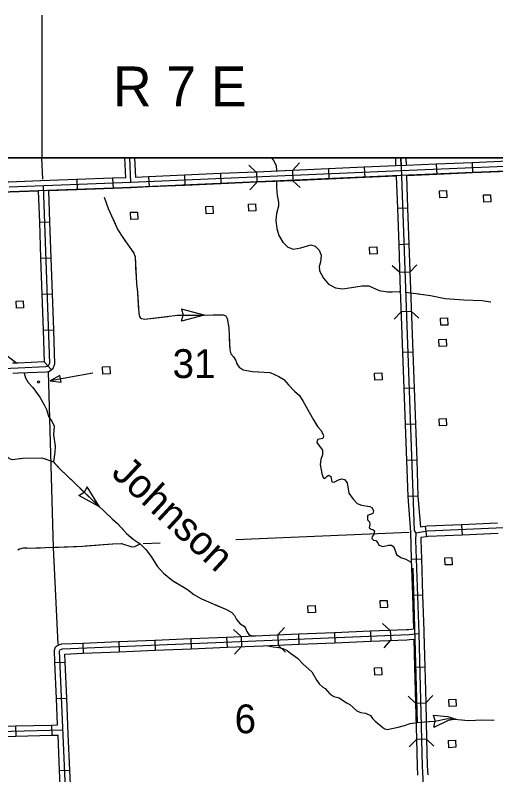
# Model space of a CAD drawing. Extents: x -0.3 to 2.65, y 0 to 1.9.
# Drawn here: x 0.4946 to 0.579, y 0.4334 to 0.5667 of the extents above; entities that cross this region are included whole.
import ezdxf

# ---------------------------------------------------------------- set-up
doc = ezdxf.new("R2010")
doc.units = 0
for name, color, linetype in [('DSN_DRFT_DNC', 7, 'Continuous'), ('Level 11', 7, 'Continuous'), ('Level 12', 7, 'Continuous'), ('Level 14', 7, 'Continuous'), ('Level 15', 7, 'Continuous'), ('Level 18', 7, 'Continuous'), ('Level 19', 7, 'Continuous'), ('Level 20', 7, 'Continuous'), ('Level 29', 7, 'Continuous'), ('Level 6', 7, 'Continuous'), ('SHET_Annotations', 7, 'Continuous')]:
    doc.layers.add(name, color=color, linetype=linetype)

msp = doc.modelspace()

# ---------------------------------------------------------------- linework, layer by layer
at = {"layer": 'DSN_DRFT_DNC'}
msp.add_lwpolyline([(0.38477, 0.54167), (1.0319, 0.54167), (1.0319, 0.1443), (0.38477, 0.1443)], close=True, dxfattribs=at)
at = {"layer": 'Level 11'}
msp.add_line((0.49949, 0.53788), (0.49934, 0.54164), dxfattribs=at)
for points in [[(0.50045, 0.50408), (0.50131, 0.47332), (0.50213, 0.45632)], [(0.53337, 0.47469), (0.56377, 0.476)], [(0.5171, 0.474), (0.52007, 0.47412)]]:
    msp.add_lwpolyline(points, dxfattribs=at)
at = {"layer": 'Level 12'}
for p, q in [((0.52383, 0.51509), (0.52412, 0.51404)), ((0.52781, 0.51407), (0.52383, 0.51509)), ((0.52781, 0.51407), (0.52385, 0.51297)), ((0.52385, 0.51297), (0.52412, 0.51402)), ((0.56802, 0.44388), (0.56835, 0.44283)), ((0.56811, 0.44175), (0.56835, 0.44282))]:
    msp.add_line(p, q, dxfattribs=at)
for points in [[(0.51023, 0.53476), (0.51094, 0.53273), (0.51103, 0.53253)], [(0.5117, 0.5311), (0.51266, 0.52904), (0.51367, 0.52747), (0.51402, 0.52698)], [(0.51493, 0.5257), (0.51548, 0.52493), (0.51567, 0.52426), (0.51584, 0.52116)], [(0.51592, 0.51959), (0.51592, 0.51955), (0.51611, 0.51808), (0.51629, 0.51487)], [(0.56403, 0.51799), (0.56555, 0.51779)], [(0.56712, 0.51758), (0.56755, 0.51752), (0.57009, 0.51699), (0.57179, 0.51686)], [(0.57337, 0.51675), (0.57338, 0.51675), (0.57658, 0.5166), (0.57809, 0.51639)], [(0.5168, 0.51348), (0.51733, 0.51336), (0.5215, 0.51384)], [(0.52307, 0.51402), (0.5231, 0.51402), (0.52781, 0.51407)], [(0.52939, 0.51409), (0.53116, 0.51411), (0.5316, 0.51394), (0.53187, 0.51346), (0.53211, 0.51182), (0.53212, 0.51154)], [(0.5322, 0.50996), (0.53229, 0.50794), (0.53249, 0.50724), (0.53293, 0.50674), (0.53336, 0.50608), (0.53352, 0.50556)], [(0.56802, 0.44388), (0.5706, 0.44366), (0.57198, 0.44316), (0.57065, 0.44292), (0.56811, 0.44174)], [(0.5673, 0.44278), (0.56828, 0.44282), (0.57058, 0.4433), (0.57198, 0.44316)], [(0.57355, 0.443), (0.57417, 0.44294), (0.57674, 0.44304), (0.57828, 0.44302)]]:
    msp.add_lwpolyline(points, dxfattribs=at)
at = {"layer": 'Level 14'}
for p, q in [((0.50729, 0.48396), (0.50677, 0.483)), ((0.50943, 0.48045), (0.50729, 0.48396)), ((0.50582, 0.48242), (0.50676, 0.48299)), ((0.50943, 0.48045), (0.50582, 0.48242))]:
    msp.add_line(p, q, dxfattribs=at)
for points in [[(0.53962, 0.54164), (0.54, 0.54118), (0.54047, 0.5403), (0.54053, 0.53934)], [(0.54052, 0.53747), (0.54052, 0.53645), (0.54063, 0.53504), (0.54087, 0.53388), (0.54084, 0.53315), (0.54051, 0.53186), (0.54041, 0.53063), (0.54059, 0.52927), (0.54091, 0.52803), (0.54162, 0.52684), (0.54251, 0.52597), (0.54351, 0.52564), (0.54479, 0.52583), (0.54651, 0.52636), (0.54731, 0.52615), (0.548, 0.52545), (0.54832, 0.5246), (0.54825, 0.52337), (0.54801, 0.52256), (0.54804, 0.52183), (0.54874, 0.52054), (0.54964, 0.51948), (0.55084, 0.51883), (0.55215, 0.51867), (0.55555, 0.51918), (0.55669, 0.5192), (0.55852, 0.51838), (0.55996, 0.51816), (0.56082, 0.51813), (0.56206, 0.51817), (0.56224, 0.51816)], [(0.51023, 0.53476), (0.51094, 0.53273), (0.51266, 0.52904), (0.51367, 0.52747), (0.51548, 0.52493), (0.51567, 0.52426), (0.51592, 0.51955), (0.51611, 0.51808), (0.51632, 0.51434), (0.51644, 0.51383), (0.51666, 0.51352), (0.51733, 0.51336), (0.5231, 0.51402), (0.53116, 0.51411), (0.5316, 0.51394), (0.53187, 0.51346), (0.53211, 0.51182), (0.53229, 0.50794), (0.53249, 0.50724), (0.53293, 0.50674), (0.53336, 0.50608), (0.53354, 0.5055), (0.53393, 0.50495), (0.53467, 0.50445), (0.53628, 0.50416), (0.5394, 0.50398)], [(0.51023, 0.53476), (0.51094, 0.53273), (0.51266, 0.52904), (0.51367, 0.52747), (0.51548, 0.52493), (0.51567, 0.52426), (0.51592, 0.51955), (0.51611, 0.51808), (0.51632, 0.51434), (0.51644, 0.51383), (0.51666, 0.51352), (0.51733, 0.51336), (0.5231, 0.51402), (0.53116, 0.51411), (0.5316, 0.51394), (0.53187, 0.51346), (0.53211, 0.51182), (0.53229, 0.50794), (0.53249, 0.50724), (0.53293, 0.50674), (0.53336, 0.50608), (0.53354, 0.5055), (0.53393, 0.50495), (0.53467, 0.50445), (0.53628, 0.50416), (0.5394, 0.50398)], [(0.5632, 0.5181), (0.56755, 0.51752), (0.57009, 0.51699), (0.57338, 0.51675), (0.57658, 0.5166), (0.57813, 0.51638)], [(0.5632, 0.5181), (0.56755, 0.51752), (0.57009, 0.51699), (0.57338, 0.51675), (0.57658, 0.5166), (0.57813, 0.51638)], [(0.49222, 0.50768), (0.49487, 0.50571)], [(0.49619, 0.50386), (0.49647, 0.50308), (0.49693, 0.50221), (0.49773, 0.50138), (0.49895, 0.49965), (0.49974, 0.4983), (0.50013, 0.49748), (0.50052, 0.49617), (0.50104, 0.49546), (0.50148, 0.49455), (0.50137, 0.49308), (0.50165, 0.49105), (0.50161, 0.49004), (0.50135, 0.48831)], [(0.53462, 0.50448), (0.53467, 0.50445), (0.53628, 0.50416), (0.53932, 0.50398)], [(0.5394, 0.50398), (0.5409, 0.50331), (0.5418, 0.50277), (0.54258, 0.50182), (0.54365, 0.50071), (0.54453, 0.49995), (0.54521, 0.49889), (0.54697, 0.49567), (0.54768, 0.49453), (0.54828, 0.49387), (0.54868, 0.49313), (0.54875, 0.49274), (0.54861, 0.49241), (0.54771, 0.49221), (0.54758, 0.4917), (0.54855, 0.49039), (0.54858, 0.48955), (0.54829, 0.48873), (0.54819, 0.48788), (0.54847, 0.4863), (0.54869, 0.4856), (0.54898, 0.48541), (0.54941, 0.48581), (0.54971, 0.48596), (0.55003, 0.48577), (0.55024, 0.4848), (0.55063, 0.48475), (0.55136, 0.48518), (0.55199, 0.48533), (0.55246, 0.48523), (0.55293, 0.48462), (0.55322, 0.48282), (0.55394, 0.48178), (0.55468, 0.48102), (0.55544, 0.48071), (0.5569, 0.4805), (0.55729, 0.48026), (0.5575, 0.47974), (0.55741, 0.47925), (0.55649, 0.47891), (0.55648, 0.47816), (0.55684, 0.47779), (0.55687, 0.47731), (0.55677, 0.47674), (0.5571, 0.47649), (0.55744, 0.47645), (0.55769, 0.47621), (0.5576, 0.47556), (0.55729, 0.47523), (0.55723, 0.47485), (0.5575, 0.47459), (0.55796, 0.4745), (0.55831, 0.47413), (0.55849, 0.4737), (0.55919, 0.47345), (0.56014, 0.4737), (0.56071, 0.47373), (0.56112, 0.47339), (0.56154, 0.47204), (0.56234, 0.47156), (0.56323, 0.47127), (0.56404, 0.47078), (0.56421, 0.47062)], [(0.48372, 0.49989), (0.49284, 0.48965), (0.49359, 0.48892), (0.49408, 0.48875), (0.49597, 0.48898)], [(0.48372, 0.49989), (0.49284, 0.48965), (0.49359, 0.48892), (0.49408, 0.48875), (0.49597, 0.48898)], [(0.49538, 0.48891), (0.49597, 0.48898), (0.49933, 0.48903), (0.50007, 0.48877)], [(0.49597, 0.48898), (0.49933, 0.48903), (0.50135, 0.48831), (0.50255, 0.48701), (0.51167, 0.47832), (0.51261, 0.47749), (0.51417, 0.47575), (0.51537, 0.47476), (0.51657, 0.47395), (0.51754, 0.47297), (0.51852, 0.47171), (0.51956, 0.47003), (0.52068, 0.46877), (0.52222, 0.46749), (0.52491, 0.46592), (0.52599, 0.46503), (0.52733, 0.46427), (0.53171, 0.46243)], [(0.49597, 0.48898), (0.49933, 0.48903), (0.50135, 0.48831), (0.50255, 0.48701), (0.51167, 0.47832), (0.51261, 0.47749), (0.51417, 0.47575), (0.51537, 0.47476), (0.51657, 0.47395), (0.51754, 0.47297), (0.51852, 0.47171), (0.51956, 0.47003), (0.52068, 0.46877), (0.52222, 0.46749), (0.52491, 0.46592), (0.52599, 0.46503), (0.52733, 0.46427), (0.53171, 0.46243)], [(0.5015, 0.48815), (0.50255, 0.48701), (0.50485, 0.48481)], [(0.506, 0.48372), (0.50943, 0.48045)], [(0.51057, 0.47936), (0.51167, 0.47832), (0.51261, 0.47749), (0.51393, 0.47602)], [(0.5151, 0.47498), (0.51537, 0.47476), (0.51657, 0.47395), (0.51754, 0.47297), (0.5185, 0.47173)], [(0.4967, 0.47316), (0.49602, 0.47316), (0.49539, 0.47299), (0.49509, 0.47284)], [(0.4967, 0.47316), (0.50652, 0.47353), (0.5118, 0.47395), (0.51329, 0.47402), (0.51509, 0.4734), (0.51561, 0.47345), (0.51657, 0.47395)], [(0.4967, 0.47316), (0.50652, 0.47353), (0.5118, 0.47395), (0.51329, 0.47402), (0.51509, 0.4734), (0.51561, 0.47345), (0.51657, 0.47395)], [(0.4967, 0.47316), (0.49907, 0.47325)], [(0.50065, 0.47331), (0.50538, 0.47348)], [(0.50696, 0.47356), (0.51168, 0.47394)], [(0.51326, 0.47402), (0.51329, 0.47402), (0.51509, 0.4734), (0.51561, 0.47345), (0.51657, 0.47395)], [(0.51934, 0.47039), (0.51956, 0.47003), (0.52068, 0.46877), (0.52222, 0.46749), (0.52276, 0.46717)], [(0.56441, 0.46967), (0.56517, 0.44259)], [(0.56441, 0.46967), (0.56517, 0.44259)], [(0.52413, 0.46638), (0.52491, 0.46592), (0.52599, 0.46503), (0.52733, 0.46427), (0.52815, 0.46393)], [(0.52961, 0.46331), (0.53171, 0.46243)], [(0.53171, 0.46243), (0.53268, 0.46192), (0.53315, 0.46137), (0.53351, 0.46066), (0.5341, 0.45993), (0.53482, 0.4595), (0.53514, 0.45903), (0.53531, 0.45858), (0.53565, 0.45802), (0.53618, 0.4578), (0.5368, 0.45777)], [(0.5389, 0.45608), (0.539, 0.45603), (0.53992, 0.45584), (0.5409, 0.45573), (0.5416, 0.45557), (0.54236, 0.4552), (0.54296, 0.45474), (0.54418, 0.4539), (0.54519, 0.45283), (0.54669, 0.45146), (0.54756, 0.44999), (0.54801, 0.4494), (0.54864, 0.4488), (0.54906, 0.44856), (0.54948, 0.44812), (0.54985, 0.44762), (0.55054, 0.44716), (0.55148, 0.4469), (0.55279, 0.44602), (0.5534, 0.44577), (0.55463, 0.44462), (0.55523, 0.44435), (0.55614, 0.44423), (0.55698, 0.4438), (0.55735, 0.44328), (0.55783, 0.44281), (0.55919, 0.44169), (0.55954, 0.44148), (0.55994, 0.44139), (0.56188, 0.44176), (0.56299, 0.44207), (0.56395, 0.44244), (0.56517, 0.44259)], [(0.56517, 0.44259), (0.56648, 0.44274), (0.56828, 0.44282), (0.57058, 0.4433), (0.57417, 0.44294), (0.57674, 0.44304), (0.57869, 0.44301)], [(0.56517, 0.44259), (0.56648, 0.44274), (0.56828, 0.44282), (0.57058, 0.4433), (0.57417, 0.44294), (0.57674, 0.44304), (0.57869, 0.44301)]]:
    msp.add_lwpolyline(points, dxfattribs=at)
at = {"layer": 'Level 15'}
for p, q in [((0.51403, 0.53815), (0.51386, 0.54164)), ((0.51495, 0.5373), (0.51475, 0.54164)), ((0.51583, 0.53822), (0.51566, 0.54164)), ((0.54961, 0.53971), (0.54969, 0.53791)), ((0.55592, 0.53998), (0.556, 0.53819)), ((0.56855, 0.54052), (0.56862, 0.53873)), ((0.57486, 0.54078), (0.57493, 0.53899)), ((0.51805, 0.53832), (0.51813, 0.53653)), ((0.52436, 0.5386), (0.52444, 0.5368)), ((0.53067, 0.53887), (0.53075, 0.53708)), ((0.53698, 0.53915), (0.53706, 0.53736)), ((0.54329, 0.53943), (0.54337, 0.53763)), ((0.50543, 0.53783), (0.50549, 0.53604)), ((0.51174, 0.53806), (0.51181, 0.53627)), ((0.56352, 0.53279), (0.56172, 0.53273)), ((0.49888, 0.53036), (0.50067, 0.53042)), ((0.56374, 0.52648), (0.56195, 0.52641)), ((0.4991, 0.52404), (0.5009, 0.52411)), ((0.56392, 0.52157), (0.56213, 0.52151)), ((0.49932, 0.51773), (0.50112, 0.51779)), ((0.56417, 0.51471), (0.56237, 0.51465)), ((0.49955, 0.51142), (0.50134, 0.51148)), ((0.56443, 0.50754), (0.56263, 0.50747)), ((0.49974, 0.50585), (0.50102, 0.50446)), ((0.56465, 0.50122), (0.56286, 0.50116)), ((0.56488, 0.49491), (0.56309, 0.49484)), ((0.56511, 0.48859), (0.56332, 0.48853)), ((0.56534, 0.48228), (0.56354, 0.48222)), ((0.573, 0.47727), (0.57308, 0.47548)), ((0.5666, 0.47696), (0.56686, 0.47518)), ((0.56415, 0.47124), (0.56595, 0.47129)), ((0.56436, 0.46492), (0.56615, 0.46498)), ((0.55069, 0.45838), (0.55076, 0.45659)), ((0.557, 0.45865), (0.55708, 0.45685)), ((0.56047, 0.45879), (0.56055, 0.457)), ((0.51912, 0.45705), (0.5192, 0.45526)), ((0.52544, 0.45732), (0.52551, 0.45553)), ((0.53175, 0.45758), (0.53182, 0.45579)), ((0.5343, 0.45769), (0.53438, 0.4559)), ((0.54071, 0.45796), (0.54078, 0.45617)), ((0.54437, 0.45812), (0.54445, 0.45632)), ((0.5065, 0.45652), (0.50657, 0.45473)), ((0.51281, 0.45679), (0.51289, 0.455)), ((0.50162, 0.4531), (0.50341, 0.45317)), ((0.56473, 0.4523), (0.56653, 0.45234)), ((0.50189, 0.44678), (0.50368, 0.44686)), ((0.56489, 0.44598), (0.56669, 0.44603)), ((0.49471, 0.44199), (0.49475, 0.44019)), ((0.50102, 0.44215), (0.50107, 0.44036)), ((0.56506, 0.43966), (0.56685, 0.43971)), ((0.50244, 0.43416), (0.50423, 0.43424))]:
    msp.add_line(p, q, dxfattribs=at)
for points in [[(0.63649, 0.54164), (0.62462, 0.5411), (0.56089, 0.53848), (0.51348, 0.53639), (0.49209, 0.5356)], [(0.61723, 0.54164), (0.56237, 0.53938), (0.51495, 0.5373), (0.49357, 0.53651)], [(0.56232, 0.54164), (0.56467, 0.4763), (0.56498, 0.47581)], [(0.58117, 0.54104), (0.57486, 0.54078)], [(0.54961, 0.53971), (0.54329, 0.53943)], [(0.55592, 0.53998), (0.54961, 0.53971)], [(0.56145, 0.54023), (0.55592, 0.53998)], [(0.56855, 0.54052), (0.56325, 0.5403)], [(0.57486, 0.54078), (0.56855, 0.54052)], [(0.51805, 0.53832), (0.51583, 0.53822)], [(0.52436, 0.5386), (0.51805, 0.53832)], [(0.53067, 0.53887), (0.52436, 0.5386)], [(0.53698, 0.53915), (0.53067, 0.53887)], [(0.54329, 0.53943), (0.53698, 0.53915)], [(0.56152, 0.53843), (0.556, 0.53819)], [(0.56152, 0.53843), (0.56172, 0.53273)], [(0.56862, 0.53873), (0.56331, 0.53851)], [(0.56331, 0.53851), (0.56352, 0.53279)], [(0.57493, 0.53899), (0.56862, 0.53873)], [(0.58125, 0.53925), (0.57493, 0.53899)], [(0.49911, 0.5376), (0.49353, 0.53739), (0.49278, 0.53735)], [(0.50543, 0.53783), (0.49911, 0.5376)], [(0.51174, 0.53806), (0.50543, 0.53783)], [(0.51403, 0.53815), (0.51174, 0.53806)], [(0.53075, 0.53708), (0.52444, 0.5368)], [(0.53706, 0.53736), (0.53075, 0.53708)], [(0.54337, 0.53763), (0.53706, 0.53736)], [(0.54969, 0.53791), (0.54337, 0.53763)], [(0.556, 0.53819), (0.54969, 0.53791)], [(0.49869, 0.53579), (0.49361, 0.5356), (0.49288, 0.53556)], [(0.49954, 0.5367), (0.50063, 0.5056), (0.50048, 0.5052), (0.50027, 0.50503), (0.49999, 0.50497), (0.49517, 0.50476)], [(0.49869, 0.53579), (0.49888, 0.53036)], [(0.50549, 0.53604), (0.50048, 0.53585)], [(0.50048, 0.53585), (0.50067, 0.53042)], [(0.51181, 0.53627), (0.50549, 0.53604)], [(0.51813, 0.53653), (0.51499, 0.53639), (0.51181, 0.53627)], [(0.52444, 0.5368), (0.51813, 0.53653)], [(0.56172, 0.53273), (0.56195, 0.52641)], [(0.56352, 0.53279), (0.56374, 0.52648)], [(0.49888, 0.53036), (0.4991, 0.52404)], [(0.50067, 0.53042), (0.5009, 0.52411)], [(0.56195, 0.52641), (0.56218, 0.5201)], [(0.56374, 0.52648), (0.56397, 0.52017)], [(0.4991, 0.52404), (0.49932, 0.51773)], [(0.5009, 0.52411), (0.50112, 0.51779)], [(0.56218, 0.5201), (0.5624, 0.51379)], [(0.56397, 0.52017), (0.5642, 0.51385)], [(0.49932, 0.51773), (0.49955, 0.51142)], [(0.50112, 0.51779), (0.50134, 0.51148)], [(0.5624, 0.51379), (0.56263, 0.50747)], [(0.5642, 0.51385), (0.56443, 0.50754)], [(0.49955, 0.51142), (0.49974, 0.50584)], [(0.50134, 0.51148), (0.50155, 0.50545), (0.50125, 0.50464), (0.50102, 0.50446)], [(0.56263, 0.50747), (0.56286, 0.50116)], [(0.56443, 0.50754), (0.56465, 0.50122)], [(0.49974, 0.50584), (0.49514, 0.50564), (0.49415, 0.5056)], [(0.49517, 0.50476), (0.48584, 0.50435), (0.48532, 0.50423), (0.48479, 0.5039), (0.48424, 0.50328), (0.47058, 0.48157), (0.4661, 0.47335), (0.46544, 0.47185), (0.46338, 0.46658), (0.45868, 0.45792), (0.458, 0.45682), (0.45676, 0.45523), (0.44502, 0.44176), (0.44413, 0.44088), (0.44253, 0.44009), (0.43966, 0.43912)], [(0.50102, 0.50446), (0.50068, 0.50419), (0.50011, 0.50406), (0.49522, 0.50385), (0.49423, 0.5038)], [(0.56286, 0.50116), (0.56309, 0.49484)], [(0.56465, 0.50122), (0.56488, 0.49491)], [(0.56309, 0.49484), (0.56332, 0.48853)], [(0.56488, 0.49491), (0.56511, 0.48859)], [(0.56332, 0.48853), (0.56354, 0.48222)], [(0.56511, 0.48859), (0.56534, 0.48228)], [(0.56354, 0.48222), (0.56401, 0.47597)], [(0.56534, 0.48228), (0.56578, 0.47684)], [(0.65507, 0.47962), (0.65429, 0.47984), (0.65142, 0.4798), (0.62875, 0.47887), (0.56702, 0.47613), (0.56558, 0.47592), (0.56498, 0.47581), (0.56493, 0.47458), (0.56546, 0.45822), (0.56606, 0.43494), (0.56734, 0.41056)], [(0.573, 0.47727), (0.56694, 0.47701), (0.5666, 0.47696)], [(0.57931, 0.47755), (0.573, 0.47727)], [(0.56401, 0.47604), (0.56415, 0.47124)], [(0.5666, 0.47696), (0.56578, 0.47684)], [(0.57939, 0.47576), (0.57308, 0.47548)], [(0.56686, 0.47518), (0.56586, 0.47504), (0.56584, 0.47458), (0.56595, 0.47129)], [(0.57308, 0.47548), (0.56711, 0.47522), (0.56686, 0.47518)], [(0.56415, 0.47124), (0.56436, 0.46492)], [(0.56595, 0.47129), (0.56615, 0.46498)], [(0.56436, 0.46492), (0.56455, 0.45901)], [(0.56615, 0.46498), (0.56636, 0.45866)], [(0.54437, 0.45812), (0.55069, 0.45838)], [(0.55069, 0.45838), (0.557, 0.45865)], [(0.557, 0.45865), (0.56331, 0.45891)], [(0.56331, 0.45891), (0.56373, 0.45893), (0.56455, 0.45901)], [(0.56636, 0.45866), (0.56637, 0.45825), (0.56653, 0.45234)], [(0.504, 0.40911), (0.50439, 0.4095), (0.50241, 0.45518), (0.50245, 0.45531), (0.50261, 0.45542), (0.50292, 0.45549), (0.56379, 0.45805), (0.56546, 0.45822)], [(0.51281, 0.45679), (0.51912, 0.45705)], [(0.51912, 0.45705), (0.52544, 0.45732)], [(0.52544, 0.45732), (0.53175, 0.45758)], [(0.53175, 0.45758), (0.53806, 0.45785)], [(0.53806, 0.45785), (0.54437, 0.45812)], [(0.55708, 0.45685), (0.56339, 0.45712)], [(0.56339, 0.45712), (0.56386, 0.45714), (0.56461, 0.45721)], [(0.56461, 0.45721), (0.56473, 0.4523)], [(0.50162, 0.4531), (0.50152, 0.4553), (0.5017, 0.45589), (0.50226, 0.45624), (0.5028, 0.45637), (0.5065, 0.45652)], [(0.5065, 0.45652), (0.51281, 0.45679)], [(0.52551, 0.45553), (0.53182, 0.45579)], [(0.53182, 0.45579), (0.53814, 0.45606)], [(0.53814, 0.45606), (0.54445, 0.45632)], [(0.54445, 0.45632), (0.55076, 0.45659)], [(0.55076, 0.45659), (0.55708, 0.45685)], [(0.50341, 0.45317), (0.50335, 0.45459), (0.50657, 0.45473)], [(0.50657, 0.45473), (0.51289, 0.455)], [(0.51289, 0.455), (0.5192, 0.45526)], [(0.5192, 0.45526), (0.52551, 0.45553)], [(0.50189, 0.44678), (0.50162, 0.4531)], [(0.50368, 0.44686), (0.50341, 0.45317)], [(0.56473, 0.4523), (0.56489, 0.44598)], [(0.56653, 0.45234), (0.56669, 0.44603)], [(0.50209, 0.44218), (0.50189, 0.44678)], [(0.50396, 0.44055), (0.50368, 0.44686)], [(0.56489, 0.44598), (0.56506, 0.43966)], [(0.56669, 0.44603), (0.56685, 0.43971)], [(0.44502, 0.44176), (0.44628, 0.44033), (0.44683, 0.43992), (0.44739, 0.43972), (0.47132, 0.4405), (0.50301, 0.44132)], [(0.48839, 0.44182), (0.49471, 0.44199)], [(0.49471, 0.44199), (0.50102, 0.44215)], [(0.50102, 0.44215), (0.50209, 0.44218)], [(0.48844, 0.44003), (0.49475, 0.44019)], [(0.49475, 0.44019), (0.50107, 0.44036)], [(0.50107, 0.44036), (0.50217, 0.44038)], [(0.50244, 0.43416), (0.50217, 0.44038)], [(0.50423, 0.43424), (0.50396, 0.44055)], [(0.56506, 0.43966), (0.56518, 0.43491), (0.56526, 0.43333)], [(0.56685, 0.43971), (0.56697, 0.43498), (0.56705, 0.43342)], [(0.50271, 0.42785), (0.50244, 0.43416)], [(0.50451, 0.42793), (0.50423, 0.43424)]]:
    msp.add_lwpolyline(points, dxfattribs=at)
at = {"layer": 'Level 18'}
for p, q in [((0.56147, 0.54023), (0.56142, 0.54164)), ((0.56237, 0.54027), (0.56232, 0.54164)), ((0.56322, 0.54164), (0.56326, 0.5403)), ((0.56326, 0.5403), (0.56147, 0.54023))]:
    msp.add_line(p, q, dxfattribs=at)
at = {"layer": 'Level 19'}
for points in [[(0.56916, 0.5346), (0.56911, 0.53585), (0.57036, 0.5359), (0.57041, 0.53466)], [(0.5769, 0.53388), (0.57684, 0.53513), (0.57809, 0.53518), (0.57815, 0.53394)], [(0.52815, 0.53184), (0.5281, 0.53309), (0.52935, 0.53314), (0.5294, 0.5319)], [(0.53563, 0.53227), (0.53557, 0.53351), (0.53682, 0.53356), (0.53688, 0.53232)], [(0.51493, 0.53084), (0.51487, 0.53209), (0.51612, 0.53214), (0.51617, 0.5309)], [(0.55691, 0.52474), (0.55685, 0.52599), (0.5581, 0.52604), (0.55816, 0.5248)], [(0.49485, 0.51527), (0.49479, 0.51652), (0.49604, 0.51657), (0.4961, 0.51533)], [(0.56935, 0.51227), (0.56929, 0.51351), (0.57054, 0.51357), (0.57059, 0.51232)], [(0.56908, 0.50854), (0.56902, 0.50978), (0.57027, 0.50984), (0.57032, 0.50859)], [(0.51004, 0.50372), (0.50998, 0.50496), (0.51123, 0.50502), (0.51128, 0.50377)], [(0.55778, 0.50263), (0.55772, 0.50387), (0.55897, 0.50393), (0.55903, 0.50268)], [(0.50268, 0.50227), (0.50246, 0.50347), (0.50077, 0.50254)], [(0.56911, 0.49461), (0.56905, 0.49586), (0.5703, 0.49591), (0.57036, 0.49467)], [(0.57008, 0.47023), (0.57003, 0.47147), (0.57127, 0.47153), (0.57133, 0.47028)], [(0.55873, 0.46272), (0.55868, 0.46397), (0.55993, 0.46402), (0.55998, 0.46278)], [(0.54608, 0.46183), (0.54602, 0.46308), (0.54727, 0.46313), (0.54733, 0.46189)], [(0.55777, 0.45092), (0.55771, 0.45216), (0.55896, 0.45222), (0.55902, 0.45097)], [(0.5708, 0.4454), (0.57074, 0.44665), (0.57199, 0.4467), (0.57204, 0.44546)], [(0.57074, 0.43818), (0.57068, 0.43943), (0.57193, 0.43948), (0.57199, 0.43824)]]:
    msp.add_lwpolyline(points, close=True, dxfattribs=at)
msp.add_lwpolyline([(0.50824, 0.5039), (0.50077, 0.50254)], dxfattribs=at)
msp.add_circle((0.49872, 0.50233), 0.000179, dxfattribs=at)
at = {"layer": 'Level 29'}
for points in [[(0.53562, 0.54037), (0.53695, 0.53916)], [(0.54332, 0.53944), (0.54453, 0.54076)], [(0.53706, 0.53733), (0.53585, 0.53601)], [(0.54468, 0.53642), (0.54336, 0.53763)], [(0.56213, 0.52151), (0.56081, 0.52273)], [(0.56515, 0.52289), (0.56393, 0.52158)], [(0.56115, 0.51333), (0.56237, 0.51465)], [(0.56416, 0.51472), (0.56548, 0.5135)], [(0.5591, 0.45999), (0.56042, 0.45878)], [(0.53298, 0.45891), (0.5343, 0.45769)], [(0.54071, 0.45796), (0.54192, 0.45928)], [(0.53438, 0.4559), (0.53316, 0.45458)], [(0.54211, 0.45495), (0.54078, 0.45617)], [(0.56054, 0.45701), (0.55932, 0.45569)], [(0.56492, 0.446), (0.56362, 0.44724)], [(0.56795, 0.44735), (0.56672, 0.44605)], [(0.56381, 0.43834), (0.56505, 0.43964)], [(0.56684, 0.43968), (0.56814, 0.43845)]]:
    msp.add_lwpolyline(points, dxfattribs=at)
at = {"layer": 'Level 6'}
msp.add_lwpolyline([(1.03189, 0.54164), (1.03189, 0.54164), (0.38476, 0.54164)], dxfattribs=at)
at = {"layer": 'SHET_Annotations'}
msp.add_line((0.49932, 0.56667), (0.49932, 0.54167), dxfattribs=at)

# ---------------------------------------------------------------- texts
at = {"layer": 'Level 14'}
msp.add_text('Johnson', height=0.005055, rotation=317.1387, dxfattribs=at).set_placement((0.5113, 0.4861))
at = {"layer": 'Level 20'}
for s, height, p in [('31', 0.005055, (0.52226, 0.50302)), ('6', 0.00505, (0.53315, 0.44071))]:
    msp.add_text(s, height=height, dxfattribs=at).set_placement(p)
at = {"layer": 'SHET_Annotations'}
msp.add_text('R 7 E', height=0.007, dxfattribs=at).set_placement((0.51182, 0.55067))

doc.saveas('drawing.dxf')
